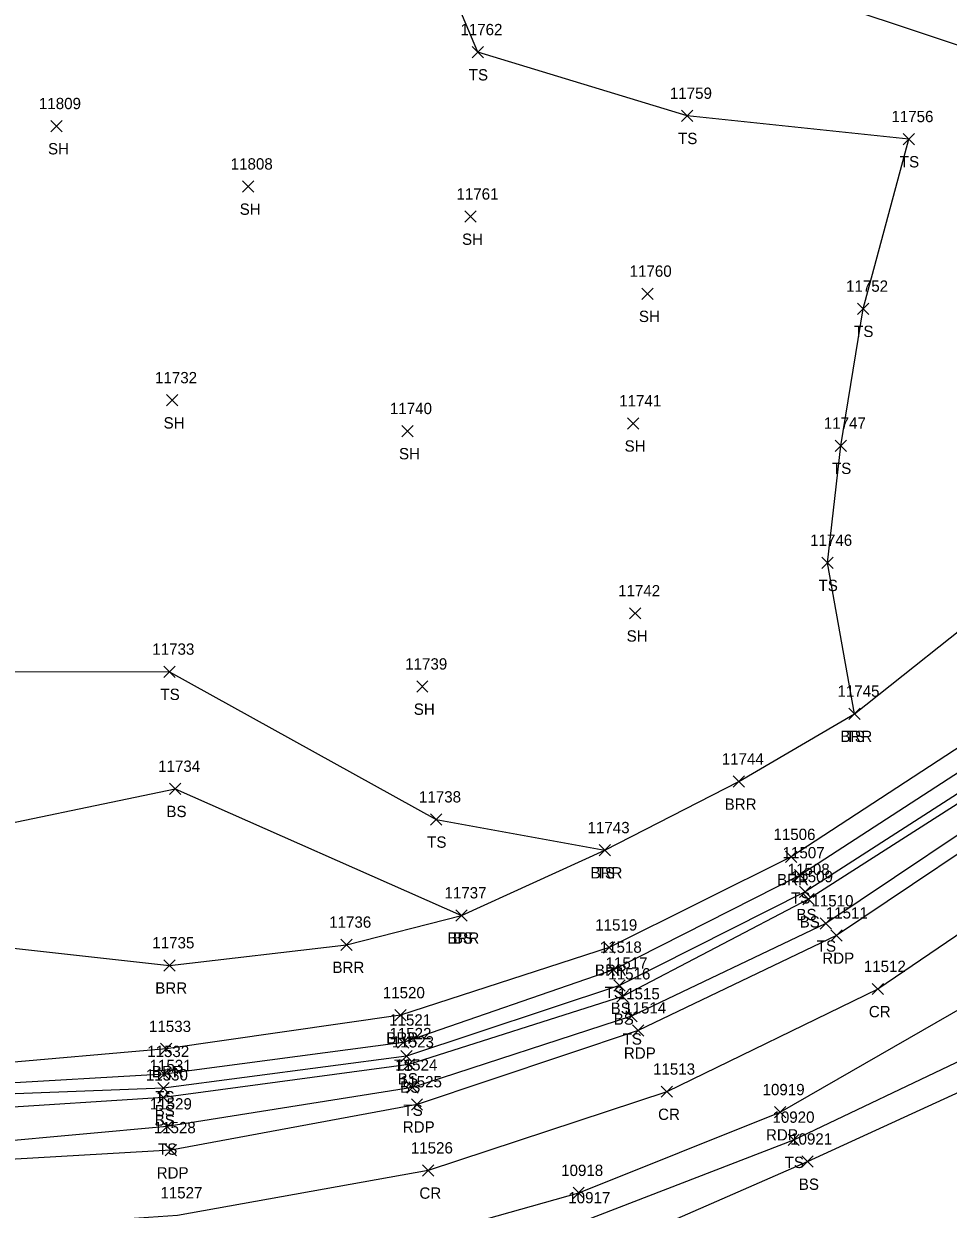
# Model space of a CAD drawing. Extents: x 1482574 to 1485769, y 580696 to 595649.
# Drawn here: x 1483140 to 1483303.5, y 582945.6 to 583155.2 of the extents above; entities that cross this region are included whole.
import ezdxf

# ---------------------------------------------------------------- set-up
doc = ezdxf.new("R2010")
doc.units = 0
for name, color, linetype in [('L_A', 7, 'Continuous'), ('L_I', 7, 'Continuous'), ('L_TIC', 7, 'Continuous'), ('LABL', 7, 'Continuous'), ('LELB', 7, 'Continuous'), ('P_A', 7, 'Continuous'), ('P_I', 7, 'Continuous'), ('P_TIC', 7, 'Continuous'), ('PET', 7, 'Continuous'), ('PRC', 7, 'Continuous')]:
    doc.layers.add(name, color=color, linetype=linetype)

msp = doc.modelspace()

# ---------------------------------------------------------------- linework, layer by layer
at = {"layer": 'L_TIC'}
for points in [[(1483219.26, 583149.18), (1483221.26, 583151.18)], [(1483221.26, 583149.18), (1483219.26, 583151.18)], [(1483144.77, 583136.11), (1483146.77, 583138.11)], [(1483146.77, 583136.11), (1483144.77, 583138.11)], [(1483256.27, 583137.93), (1483258.27, 583139.93)], [(1483258.27, 583137.93), (1483256.27, 583139.93)], [(1483295.49, 583133.81), (1483297.49, 583135.81)], [(1483297.49, 583133.81), (1483295.49, 583135.81)], [(1483178.67, 583125.43), (1483180.67, 583127.43)], [(1483180.67, 583125.43), (1483178.67, 583127.43)], [(1483217.99, 583120.12), (1483219.99, 583122.12)], [(1483219.99, 583120.12), (1483217.99, 583122.12)], [(1483249.27, 583106.48), (1483251.27, 583108.48)], [(1483251.27, 583106.48), (1483249.27, 583108.48)], [(1483287.41, 583103.83), (1483289.41, 583105.83)], [(1483289.41, 583103.83), (1483287.41, 583105.83)], [(1483165.22, 583087.65), (1483167.22, 583089.65)], [(1483167.22, 583087.65), (1483165.22, 583089.65)], [(1483206.84, 583082.2), (1483208.84, 583084.2)], [(1483208.84, 583082.2), (1483206.84, 583084.2)], [(1483246.74, 583083.56), (1483248.74, 583085.56)], [(1483248.74, 583083.56), (1483246.74, 583085.56)], [(1483283.49, 583079.61), (1483285.49, 583081.61)], [(1483285.49, 583079.61), (1483283.49, 583081.61)], [(1483281.12, 583058.91), (1483283.12, 583060.91)], [(1483283.12, 583058.91), (1483281.12, 583060.91)], [(1483247.1, 583049.98), (1483249.1, 583051.98)], [(1483249.1, 583049.98), (1483247.1, 583051.98)], [(1483164.73, 583039.66), (1483166.73, 583041.66)], [(1483166.73, 583039.66), (1483164.73, 583041.66)], [(1483209.46, 583037.04), (1483211.46, 583039.04)], [(1483211.46, 583037.04), (1483209.46, 583039.04)], [(1483285.89, 583032.23), (1483287.89, 583034.23)], [(1483287.89, 583032.23), (1483285.89, 583034.23)], [(1483285.89, 583032.23), (1483287.89, 583034.23)], [(1483287.89, 583032.23), (1483285.89, 583034.23)], [(1483165.76, 583018.96), (1483167.76, 583020.96)], [(1483167.76, 583018.96), (1483165.76, 583020.96)], [(1483265.43, 583020.25), (1483267.43, 583022.25)], [(1483267.43, 583020.25), (1483265.43, 583022.25)], [(1483211.9, 583013.54), (1483213.9, 583015.54)], [(1483213.9, 583013.54), (1483211.9, 583015.54)], [(1483241.71, 583008.11), (1483243.71, 583010.11)], [(1483243.71, 583008.11), (1483241.71, 583010.11)], [(1483241.71, 583008.11), (1483243.71, 583010.11)], [(1483243.71, 583008.11), (1483241.71, 583010.11)], [(1483274.7, 583006.91), (1483276.7, 583008.91)], [(1483276.7, 583006.91), (1483274.7, 583008.91)], [(1483276.27, 583003.67), (1483278.27, 583005.67)], [(1483278.27, 583003.67), (1483276.27, 583005.67)], [(1483277.17, 583000.73), (1483279.17, 583002.73)], [(1483279.17, 583000.73), (1483277.17, 583002.73)], [(1483277.75, 582999.44), (1483279.75, 583001.44)], [(1483279.75, 582999.44), (1483277.75, 583001.44)], [(1483216.41, 582996.58), (1483218.41, 582998.58)], [(1483218.41, 582996.58), (1483216.41, 582998.58)], [(1483216.41, 582996.58), (1483218.41, 582998.58)], [(1483218.41, 582996.58), (1483216.41, 582998.58)], [(1483280.81, 582995.17), (1483282.81, 582997.17)], [(1483282.81, 582995.17), (1483280.81, 582997.17)], [(1483196.07, 582991.4), (1483198.07, 582993.4)], [(1483198.07, 582991.4), (1483196.07, 582993.4)], [(1483242.49, 582990.9), (1483244.49, 582992.9)], [(1483244.49, 582990.9), (1483242.49, 582992.9)], [(1483164.74, 582987.75), (1483166.74, 582989.75)], [(1483166.74, 582987.75), (1483164.74, 582989.75)], [(1483243.29, 582986.97), (1483245.29, 582988.97)], [(1483245.29, 582986.97), (1483243.29, 582988.97)], [(1483244.32, 582984.17), (1483246.32, 582986.17)], [(1483246.32, 582984.17), (1483244.32, 582986.17)], [(1483244.86, 582982.26), (1483246.86, 582984.26)], [(1483246.86, 582982.26), (1483244.86, 582984.26)], [(1483205.58, 582978.93), (1483207.58, 582980.93)], [(1483207.58, 582978.93), (1483205.58, 582980.93)], [(1483246.47, 582978.74), (1483248.47, 582980.74)], [(1483248.47, 582978.74), (1483246.47, 582980.74)], [(1483164.14, 582972.97), (1483166.14, 582974.97)], [(1483166.14, 582972.97), (1483164.14, 582974.97)], [(1483206.05, 582974.1), (1483208.05, 582976.1)], [(1483208.05, 582974.1), (1483206.05, 582976.1)], [(1483206.66, 582971.69), (1483208.66, 582973.69)], [(1483208.66, 582971.69), (1483206.66, 582973.69)], [(1483163.82, 582968.54), (1483165.82, 582970.54)], [(1483165.82, 582968.54), (1483163.82, 582970.54)], [(1483207.1, 582970.23), (1483209.1, 582972.23)], [(1483209.1, 582970.23), (1483207.1, 582972.23)], [(1483163.68, 582964.39), (1483165.68, 582966.39)], [(1483165.68, 582964.39), (1483163.68, 582966.39)], [(1483163.69, 582966.06), (1483165.69, 582968.06)], [(1483165.69, 582966.06), (1483163.69, 582968.06)], [(1483207.71, 582966.14), (1483209.71, 582968.14)], [(1483209.71, 582966.14), (1483207.71, 582968.14)], [(1483164.31, 582959.27), (1483166.31, 582961.27)], [(1483166.31, 582959.27), (1483164.31, 582961.27)], [(1483275.13, 582956.92), (1483277.13, 582958.92)], [(1483277.13, 582956.92), (1483275.13, 582958.92)], [(1483277.6, 582953.06), (1483279.6, 582955.06)], [(1483279.6, 582953.06), (1483277.6, 582955.06)]]:
    msp.add_lwpolyline(points, dxfattribs=at)
at = {"layer": 'LABL'}
msp.add_lwpolyline([(1483308.84, 583029.56), (1483275.7, 583007.91), (1483243.49, 582991.9), (1483206.58, 582979.93), (1483165.14, 582973.97), (1483134.17, 582971.28), (1483117.01, 582973.8), (1483105.1, 582971.98), (1483067.28, 582976.18), (1483054.74, 582980.4), (1483048.11, 582988.78), (1483044.93, 582995.81), (1483078.13, 583000.63), (1483126.95, 582993), (1483165.74, 582988.75), (1483197.07, 582992.4), (1483217.41, 582997.58), (1483242.71, 583009.11), (1483266.43, 583021.25), (1483286.89, 583033.23), (1483312.43, 583053.51)], dxfattribs=at)
at = {"layer": 'LELB'}
for points in [[(1483469.33, 583421.95), (1483466.35, 583421.95), (1483456.79, 583407.14), (1483450.28, 583393.9), (1483447.78, 583346.95), (1483444.63, 583315.66), (1483433.7, 583275.62), (1483429.65, 583254.01), (1483417.18, 583202.74), (1483403.07, 583158.15), (1483389.35, 583122.63), (1483371.94, 583090.5), (1483346.47, 583056.7), (1483313.53, 583024.51), (1483278.17, 583001.73), (1483245.32, 582985.17), (1483207.66, 582972.69), (1483164.69, 582967.06), (1483133.76, 582965.88), (1483105.08, 582968.25), (1483066.28, 582972.49), (1483053.52, 582979.26), (1483044.91, 582987.03)], [(1483464.8, 583381.18), (1483455.44, 583346.11), (1483449.41, 583314.03), (1483439.83, 583274.39), (1483434.83, 583252.57), (1483422.19, 583203.05), (1483407.94, 583155.37), (1483393.98, 583120.7), (1483377.17, 583085.6), (1483350.54, 583052.14), (1483318.1, 583020.42), (1483281.81, 582996.17), (1483247.47, 582979.74), (1483208.71, 582967.14), (1483165.31, 582960.27), (1483134.3, 582957.42), (1483103.12, 582958.39), (1483063.43, 582961.65), (1483033.11, 582963.39), (1482992.61, 582964.71)], [(1483286.89, 583033.23), (1483282.12, 583059.91), (1483284.49, 583080.61), (1483288.41, 583104.83), (1483296.49, 583134.81), (1483257.27, 583138.93), (1483220.26, 583150.18), (1483199.86, 583198.56), (1483165.11, 583212.59), (1483124.1, 583214), (1483076.09, 583221.79), (1483050.34, 583219.77), (1483017.74, 583228.84), (1483001.18, 583264.72), (1483025.79, 583292.65), (1483054.85, 583318.4), (1483086.29, 583347.06), (1483117.55, 583352.51), (1483141.77, 583367.62), (1483111.59, 583380.93)], [(1483331.31, 583069.5), (1483312.61, 583093.44), (1483331.2, 583124.78), (1483308.26, 583150.34), (1483274.8, 583161.58), (1483232.28, 583179.07), (1483247.59, 583214.27), (1483205.37, 583225.3), (1483178.45, 583242), (1483140.97, 583246.57)], [(1483039.41, 582934.08), (1483085.73, 582930.68), (1483121.3, 582925.42), (1483151.79, 582925.09), (1483174.26, 582929.72), (1483189.46, 582932.26), (1483207.39, 582934.55), (1483239.37, 582943.68), (1483276.13, 582957.92), (1483307.35, 582972.77), (1483318.64, 582980.74), (1483349.12, 583001.76), (1483367.88, 583017.28), (1483397.43, 583056.38), (1483403.59, 583067.21), (1483413.49, 583085.13)], [(1483022.27, 583067.43), (1483073.72, 583059.93), (1483126.95, 583040.68), (1483165.73, 583040.66), (1483212.9, 583014.54), (1483242.71, 583009.11)], [(1483033.04, 583038.39), (1483079.92, 583034.7), (1483125.96, 583011.45), (1483166.76, 583019.96), (1483217.41, 582997.58)], [(1483310.98, 583026.58), (1483277.27, 583004.67), (1483244.29, 582987.97), (1483207.05, 582975.1), (1483164.82, 582969.54), (1483134.28, 582967.76), (1483117.01, 582973.8), (1483105, 582977.64), (1483070.72, 582989.06), (1483044.93, 582995.81)], [(1483315.19, 583023.75), (1483278.75, 583000.44), (1483245.86, 582983.26), (1483208.1, 582971.23), (1483164.68, 582965.39), (1483133.44, 582963.41), (1483104.33, 582963.01), (1483063.93, 582963.69), (1483056.8, 582965.53), (1483033.42, 582965.98), (1482992.88, 582966.8)], [(1483188.37, 582926.13), (1483207.14, 582929.7), (1483240.46, 582937.41), (1483278.6, 582954.06), (1483310.6, 582968.76)]]:
    msp.add_lwpolyline(points, dxfattribs=at)
at = {"layer": 'P_TIC'}
for points in [[(1483282.7, 582993.02), (1483284.7, 582995.02)], [(1483284.7, 582993.02), (1483282.7, 582995.02)], [(1483289.99, 582983.57), (1483291.99, 582985.57)], [(1483291.99, 582983.57), (1483289.99, 582985.57)], [(1483247.61, 582976.24), (1483249.61, 582978.24)], [(1483249.61, 582976.24), (1483247.61, 582978.24)], [(1483252.72, 582965.42), (1483254.72, 582967.42)], [(1483254.72, 582965.42), (1483252.72, 582967.42)], [(1483208.52, 582963.18), (1483210.52, 582965.18)], [(1483210.52, 582963.18), (1483208.52, 582965.18)], [(1483272.74, 582961.79), (1483274.74, 582963.79)], [(1483274.74, 582961.79), (1483272.74, 582963.79)], [(1483164.99, 582955.07), (1483166.99, 582957.07)], [(1483166.99, 582955.07), (1483164.99, 582957.07)], [(1483210.51, 582951.49), (1483212.51, 582953.49)], [(1483212.51, 582951.49), (1483210.51, 582953.49)], [(1483237.11, 582947.51), (1483239.11, 582949.51)], [(1483239.11, 582947.51), (1483237.11, 582949.51)]]:
    msp.add_lwpolyline(points, dxfattribs=at)
at = {"layer": 'PET'}
for points in [[(1483511.92, 583571.09), (1483496.28, 583508.73), (1483487.22, 583470.03), (1483474.79, 583419.59), (1483466.19, 583381.57), (1483457.71, 583345.65), (1483450.2, 583313.7), (1483440.82, 583274.3), (1483435.83, 583252.18), (1483423.1, 583202.8), (1483409.25, 583154.54), (1483397.16, 583119.52), (1483379.57, 583084.11), (1483352.88, 583049.38), (1483319.73, 583018.16), (1483283.7, 582994.02), (1483248.61, 582977.24), (1483209.52, 582964.18), (1483165.99, 582956.07), (1483134.36, 582954.23), (1483102.75, 582955.66), (1483067.48, 582958.18), (1483032.8, 582960.58), (1482992.37, 582962.35)], [(1483039.45, 582936.9), (1483076.31, 582934.62), (1483122.19, 582931.74), (1483152.07, 582932.03), (1483171.01, 582933.64), (1483190.95, 582936.44), (1483207.37, 582939.88), (1483238.11, 582948.51), (1483273.74, 582962.79), (1483311.58, 582984.53)]]:
    msp.add_lwpolyline(points, dxfattribs=at)
at = {"layer": 'PRC'}
msp.add_lwpolyline([(1483327.65, 583009.41), (1483290.99, 582984.57), (1483253.72, 582966.42), (1483211.51, 582952.49), (1483167.16, 582944.55), (1483134.63, 582942.3), (1483100.68, 582943.89), (1483060.31, 582946.71), (1483030.35, 582948.86), (1482992.83, 582951.06)], dxfattribs=at)

# ---------------------------------------------------------------- texts
at = {"layer": 'L_A'}
for s, p in [('TS', (1483218.67, 583145.18)), ('SH', (1483144.26, 583132.11)), ('TS', (1483255.68, 583133.93)), ('TS', (1483294.9, 583129.81)), ('SH', (1483178.16, 583121.43)), ('SH', (1483217.48, 583116.12)), ('SH', (1483248.76, 583102.48)), ('TS', (1483286.82, 583099.83)), ('SH', (1483164.7, 583083.65)), ('SH', (1483246.23, 583079.56)), ('SH', (1483206.33, 583078.2)), ('TS', (1483282.9, 583075.61)), ('TS', (1483280.53, 583054.91)), ('SH', (1483246.59, 583045.98)), ('TS', (1483164.14, 583035.66)), ('SH', (1483208.95, 583033.04)), ('BRR', (1483284.38, 583028.23)), ('TS', (1483285.3, 583028.23)), ('BS', (1483165.2, 583014.96)), ('BRR', (1483263.92, 583016.25)), ('TS', (1483211.31, 583009.54)), ('BRR', (1483240.2, 583004.11)), ('TS', (1483241.12, 583004.11)), ('BRR', (1483273.19, 583002.91)), ('TS', (1483275.68, 582999.67)), ('BS', (1483276.61, 582996.73)), ('BS', (1483277.19, 582995.44)), ('BRR', (1483214.89, 582992.58)), ('BS', (1483215.85, 582992.58)), ('TS', (1483280.22, 582991.17)), ('BRR', (1483194.56, 582987.4)), ('BRR', (1483240.98, 582986.9)), ('BRR', (1483163.23, 582983.75)), ('TS', (1483242.7, 582982.97)), ('BS', (1483243.76, 582980.17)), ('BS', (1483244.3, 582978.26)), ('BRR', (1483204.07, 582974.93)), ('TS', (1483245.88, 582974.74)), ('BRR', (1483162.63, 582968.97)), ('TS', (1483205.46, 582970.1)), ('BS', (1483206.11, 582967.69)), ('TS', (1483163.23, 582964.54)), ('BS', (1483206.54, 582966.23)), ('TS', (1483207.12, 582962.14)), ('BS', (1483163.12, 582960.39)), ('BS', (1483163.13, 582962.06)), ('TS', (1483163.71, 582955.27)), ('TS', (1483274.54, 582952.92)), ('BS', (1483277.04, 582949.06))]:
    msp.add_text(s, height=2, dxfattribs=at).set_placement(p)
at = {"layer": 'L_I'}
for s, p in [('11762', (1483217.19, 583153.18)), ('11759', (1483254.24, 583141.93)), ('11809', (1483142.66, 583140.11)), ('11756', (1483293.41, 583137.81)), ('11808', (1483176.57, 583129.43)), ('11761', (1483216.49, 583124.12)), ('11760', (1483247.12, 583110.48)), ('11752', (1483285.39, 583107.83)), ('11732', (1483163.19, 583091.65)), ('11740', (1483204.73, 583086.2)), ('11741', (1483245.28, 583087.56)), ('11747', (1483281.46, 583083.61)), ('11746', (1483279.04, 583062.91)), ('11742', (1483245.08, 583053.98)), ('11733', (1483162.71, 583043.66)), ('11739', (1483207.43, 583041.04)), ('11745', (1483283.87, 583036.23)), ('11745', (1483283.87, 583036.23)), ('11734', (1483163.74, 583022.96)), ('11744', (1483263.41, 583024.25)), ('11738', (1483209.87, 583017.54)), ('11743', (1483239.68, 583012.11)), ('11743', (1483239.68, 583012.11)), ('11506', (1483272.55, 583010.91)), ('11507', (1483274.17, 583007.67)), ('11508', (1483275.07, 583004.73)), ('11509', (1483275.64, 583003.44)), ('11737', (1483214.38, 583000.58)), ('11737', (1483214.38, 583000.58)), ('11510', (1483279.27, 582999.17)), ('11736', (1483193.99, 582995.4)), ('11519', (1483241.03, 582994.9)), ('11735', (1483162.71, 582991.75)), ('11518', (1483241.83, 582990.97)), ('11517', (1483242.86, 582988.17)), ('11516', (1483243.35, 582986.26)), ('11520', (1483203.47, 582982.93)), ('11515', (1483245.02, 582982.74)), ('11533', (1483162.12, 582976.97)), ('11521', (1483204.59, 582978.1)), ('11522', (1483204.64, 582975.69)), ('11523', (1483205.08, 582974.23)), ('11532', (1483161.8, 582972.54)), ('11530', (1483161.57, 582968.39)), ('11531', (1483162.23, 582970.06)), ('11524', (1483205.68, 582970.14)), ('11529', (1483162.27, 582963.27)), ('10920', (1483272.38, 582960.92)), ('10921', (1483275.5, 582957.06)), ('10917', (1483236.27, 582946.68))]:
    msp.add_text(s, height=2, dxfattribs=at).set_placement(p)
at = {"layer": 'P_A'}
for s, p in [('RDP', (1483281.19, 582989.02)), ('CR', (1483289.42, 582979.57)), ('RDP', (1483246.1, 582972.24)), ('CR', (1483252.15, 582961.42)), ('RDP', (1483207, 582959.18)), ('RDP', (1483271.23, 582957.79)), ('RDP', (1483163.48, 582951.07)), ('CR', (1483209.94, 582947.49))]:
    msp.add_text(s, height=2, dxfattribs=at).set_placement(p)
at = {"layer": 'P_I'}
for s, p in [('11511', (1483281.81, 582997.02)), ('11512', (1483288.53, 582987.57)), ('11514', (1483246.15, 582980.24)), ('11513', (1483251.26, 582969.42)), ('11525', (1483206.49, 582967.18)), ('10919', (1483270.63, 582965.79)), ('11528', (1483162.96, 582959.07)), ('11526', (1483208.43, 582955.49)), ('10918', (1483235.01, 582951.51)), ('11527', (1483164.14, 582947.55))]:
    msp.add_text(s, height=2, dxfattribs=at).set_placement(p)

doc.saveas('drawing.dxf')
